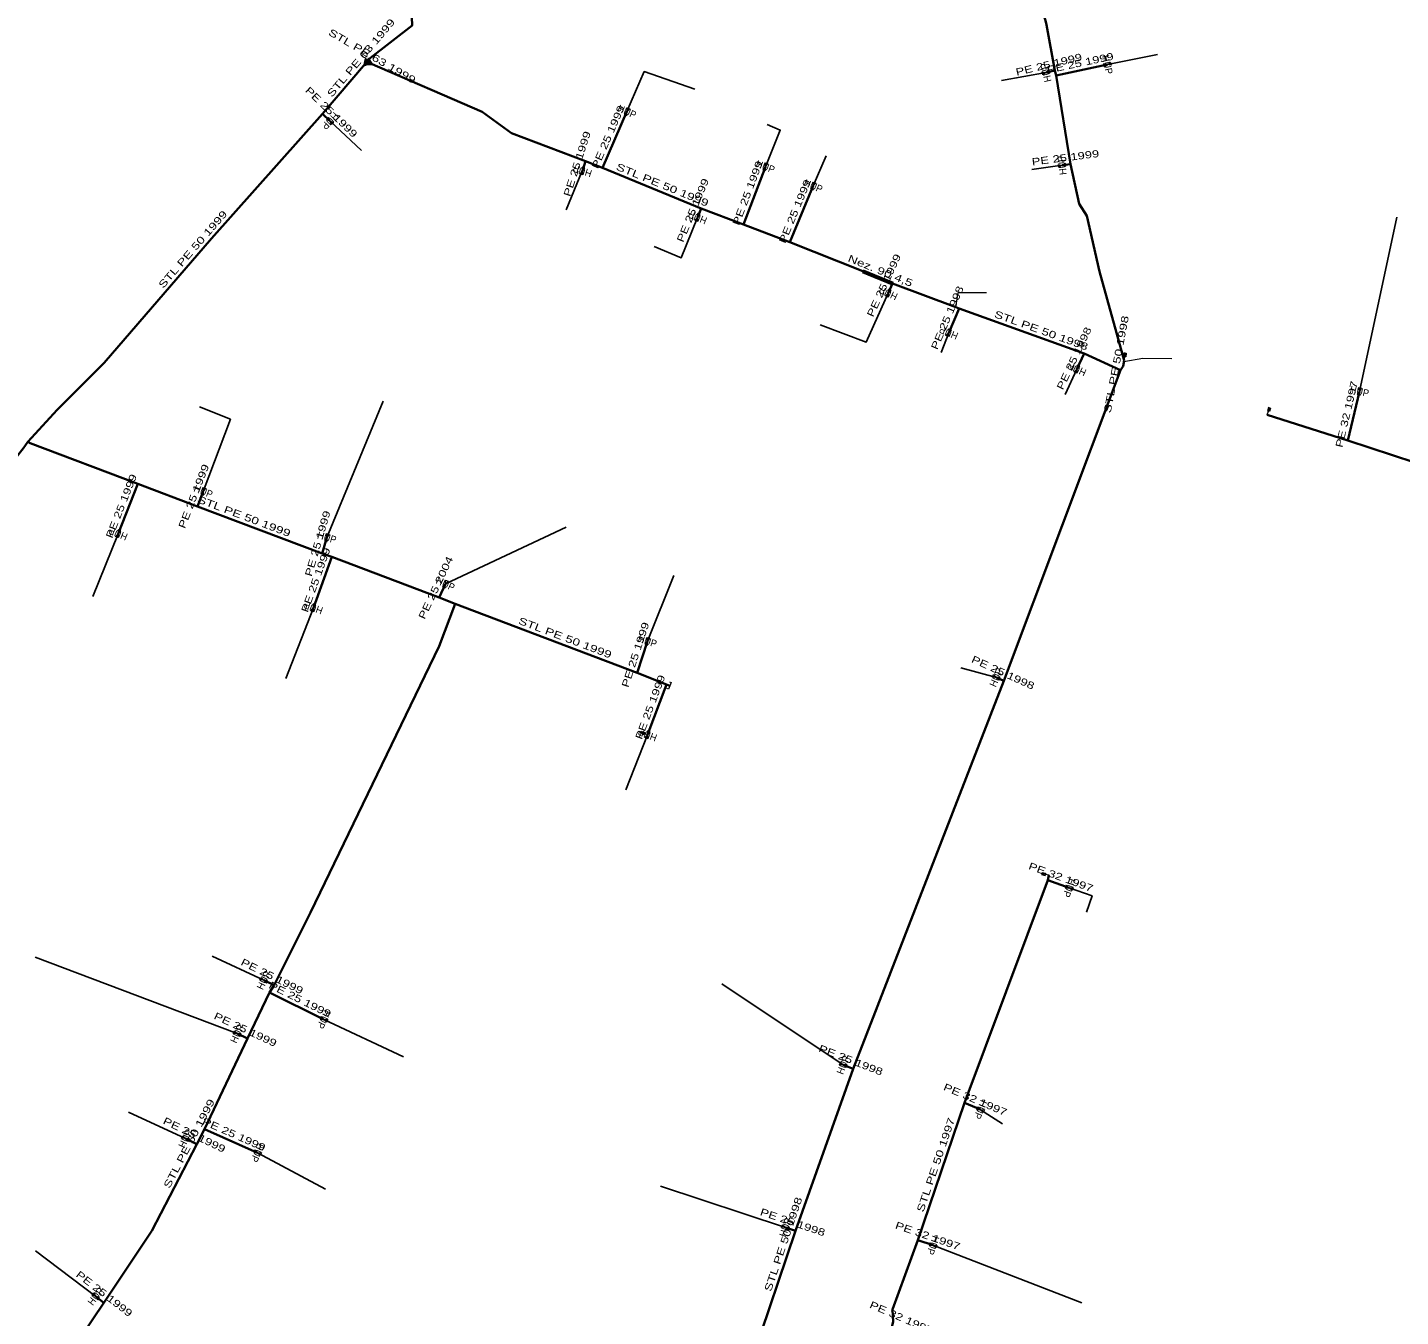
# Model space of a CAD drawing. Extents: x -737484 to -734496, y -1033882 to -1030666.
# Drawn here: x -736256.4 to -736065.4, y -1032475.7 to -1032296.4 of the extents above; entities that cross this region are included whole.
import ezdxf
from ezdxf.enums import TextEntityAlignment as Align

# ---------------------------------------------------------------- set-up
doc = ezdxf.new("R2010")
doc.units = 0
doc.header["$LTSCALE"] = 0.4
for name, color, linetype, lineweight in [('1', 7, 'Continuous', 13), ('18', 7, 'Continuous', 60), ('22', 7, 'Continuous', 25), ('5', 7, 'Continuous', 35), ('7', 7, 'Continuous', 35)]:
    doc.layers.add(name, color=color, linetype=linetype, lineweight=lineweight)
doc.layers.add('2', color=7, linetype='Continuous')

msp = doc.modelspace()

# ---------------------------------------------------------------- linework, layer by layer
at = {"layer": '1'}
for p, q in [((-736103.838, -1032342.709), (-736103.785, -1032342.211)), ((-736103.703, -1032342.144), (-736103.666, -1032341.796)), ((-736083.95, -1032350.269), (-736083.795, -1032349.793)), ((-736083.7, -1032349.745), (-736083.592, -1032349.412)), ((-736170.669, -1032394.513), (-736170.996, -1032394.388)), ((-736170.16, -1032394.79), (-736170.626, -1032394.61)), ((-736114.868, -1032414.107), (-736115.208, -1032414.022)), ((-736114.329, -1032414.319), (-736114.814, -1032414.198))]:
    msp.add_line(p, q, dxfattribs=at)
for points in [[(-736208.663, -1032301.356), (-736209.429, -1032300.713), (-736209.689, -1032301.801)], [(-736209.369, -1032300.894), (-736209.545, -1032301.629), (-736208.851, -1032301.328)], [(-736208.953, -1032300.696), (-736209.453, -1032301.563), (-736208.336, -1032301.63)], [(-736209.402, -1032301.458), (-736209.04, -1032301.301), (-736209.31, -1032301.074)], [(-736209.285, -1032301.472), (-736208.53, -1032301.518), (-736208.947, -1032300.887)], [(-736208.724, -1032301.406), (-736208.941, -1032301.077), (-736209.118, -1032301.383)], [(-736115.17, -1032302.994), (-736115.26, -1032302.604), (-736114.195, -1032302.769), (-736114.285, -1032302.379)], [(-736105.741, -1032301.288), (-736105.658, -1032301.679), (-736106.719, -1032301.496), (-736106.636, -1032301.887)], [(-736172.998, -1032307.58), (-736172.632, -1032307.743), (-736173.405, -1032308.494), (-736173.039, -1032308.657)], [(-736213.829, -1032309.612), (-736214.107, -1032309.9), (-736214.548, -1032308.917), (-736214.826, -1032309.205)], [(-736179.191, -1032316.915), (-736179.571, -1032316.791), (-736178.882, -1032315.964), (-736179.262, -1032315.84)], [(-736153.775, -1032315.24), (-736153.402, -1032315.383), (-736154.133, -1032316.174), (-736153.76, -1032316.317)], [(-736112.96, -1032315.849), (-736113.009, -1032315.452), (-736111.968, -1032315.727), (-736112.017, -1032315.33)], [(-736147.097, -1032317.921), (-736146.729, -1032318.077), (-736147.488, -1032318.842), (-736147.12, -1032318.998)], [(-736163.211, -1032323.387), (-736163.579, -1032323.231), (-736162.82, -1032322.466), (-736163.188, -1032322.31)], [(-736136.71, -1032333.915), (-736137.072, -1032333.746), (-736136.287, -1032333.009), (-736136.649, -1032332.84)], [(-736128.278, -1032339.416), (-736128.646, -1032339.26), (-736127.887, -1032338.495), (-736128.255, -1032338.339)], [(-736103.733, -1032341.714), (-736103.882, -1032341.698), (-736103.934, -1032342.196), (-736103.785, -1032342.211)], [(-736103.733, -1032341.714), (-736103.584, -1032341.73), (-736103.636, -1032342.227), (-736103.785, -1032342.211)], [(-736103.7, -1032341.756), (-736103.626, -1032341.763), (-736103.67, -1032342.186), (-736103.745, -1032342.178)], [(-736110.459, -1032344.474), (-736110.821, -1032344.305), (-736110.036, -1032343.568), (-736110.398, -1032343.399)], [(-736071.211, -1032346.496), (-736070.821, -1032346.586), (-736071.436, -1032347.471), (-736071.046, -1032347.561)], [(-736083.64, -1032349.317), (-736083.783, -1032349.271), (-736083.938, -1032349.747), (-736083.795, -1032349.793)], [(-736083.64, -1032349.317), (-736083.498, -1032349.364), (-736083.652, -1032349.839), (-736083.795, -1032349.793)], [(-736083.617, -1032349.365), (-736083.546, -1032349.388), (-736083.677, -1032349.792), (-736083.748, -1032349.769)], [(-736231.955, -1032360.389), (-736231.582, -1032360.532), (-736232.313, -1032361.323), (-736231.94, -1032361.466)], [(-736243.798, -1032367.366), (-736244.169, -1032367.216), (-736243.424, -1032366.439), (-736243.795, -1032366.289)], [(-736214.812, -1032366.812), (-736214.427, -1032366.922), (-736215.088, -1032367.773), (-736214.703, -1032367.883)], [(-736198.239, -1032373.272), (-736197.877, -1032373.441), (-736198.662, -1032374.178), (-736198.3, -1032374.347)], [(-736216.62, -1032377.667), (-736216.995, -1032377.53), (-736216.278, -1032376.727), (-736216.653, -1032376.59)], [(-736170.212, -1032381.239), (-736169.832, -1032381.363), (-736170.521, -1032382.19), (-736170.141, -1032382.314)], [(-736122.176, -1032386.788), (-736122.013, -1032386.422), (-736121.262, -1032387.195), (-736121.099, -1032386.829)], [(-736170.149, -1032395.328), (-736170.522, -1032395.185), (-736169.791, -1032394.394), (-736170.164, -1032394.251)], [(-736171.093, -1032394.431), (-736171.147, -1032394.571), (-736170.68, -1032394.75), (-736170.626, -1032394.61)], [(-736171.093, -1032394.431), (-736171.039, -1032394.291), (-736170.573, -1032394.47), (-736170.626, -1032394.61)], [(-736171.044, -1032394.41), (-736171.017, -1032394.34), (-736170.621, -1032394.492), (-736170.648, -1032394.563)], [(-736115.299, -1032414.077), (-736115.335, -1032414.222), (-736114.85, -1032414.343), (-736114.814, -1032414.198)], [(-736115.299, -1032414.077), (-736115.263, -1032413.931), (-736114.777, -1032414.052), (-736114.814, -1032414.198)], [(-736115.253, -1032414.05), (-736115.235, -1032413.977), (-736114.822, -1032414.08), (-736114.841, -1032414.153)], [(-736110.971, -1032416.053), (-736111.108, -1032416.428), (-736111.911, -1032415.711), (-736112.048, -1032416.086)], [(-736224.074, -1032428.878), (-736223.898, -1032428.519), (-736223.175, -1032429.316), (-736222.999, -1032428.957)], [(-736214.639, -1032434.397), (-736214.815, -1032434.756), (-736215.538, -1032433.959), (-736215.714, -1032434.318)], [(-736227.775, -1032436.317), (-736227.606, -1032435.955), (-736226.869, -1032436.74), (-736226.7, -1032436.378)], [(-736143.476, -1032440.695), (-736143.333, -1032440.322), (-736142.542, -1032441.053), (-736142.399, -1032440.68)], [(-736123.308, -1032446.925), (-736123.464, -1032447.293), (-736124.229, -1032446.534), (-736124.385, -1032446.902)], [(-736234.966, -1032450.898), (-736234.79, -1032450.539), (-736234.067, -1032451.336), (-736233.891, -1032450.977)], [(-736223.861, -1032452.928), (-736224.024, -1032453.294), (-736224.775, -1032452.521), (-736224.938, -1032452.887)], [(-736151.505, -1032463.313), (-736151.375, -1032462.935), (-736150.56, -1032463.638), (-736150.43, -1032463.26)], [(-736129.908, -1032465.753), (-736130.038, -1032466.131), (-736130.853, -1032465.428), (-736130.983, -1032465.806)], [(-736247.427, -1032472.728), (-736247.18, -1032472.413), (-736246.639, -1032473.344), (-736246.392, -1032473.029)]]:
    msp.add_lwpolyline(points, close=True, dxfattribs=at)
for points in [[(-736127.28, -1032335.31), (-736126.963, -1032333.293), (-736123.025, -1032333.293)], [(-736103.89, -1032342.85), (-736101.27, -1032342.406), (-736097.224, -1032342.432)], [(-736167.114, -1032387.412), (-736166.882, -1032387.506), (-736167.257, -1032388.433), (-736167.489, -1032388.339)]]:
    msp.add_lwpolyline(points, dxfattribs=at)
at = {"layer": '18'}
msp.add_line((-736140.229, -1032330.329), (-736136.058, -1032332.019), dxfattribs=at)
at = {"layer": '22'}
for p, q in [((-736106.19, -1032301.588), (-736099.223, -1032300.165)), ((-736114.728, -1032302.688), (-736120.899, -1032303.788)), ((-736214.329, -1032309.41), (-736209.967, -1032313.515)), ((-736147.11, -1032318.46), (-736145.317, -1032314.288)), ((-736112.489, -1032315.59), (-736116.692, -1032316.165)), ((-736179.228, -1032316.379), (-736181.489, -1032321.793)), ((-736071.129, -1032347.029), (-736065.919, -1032322.801)), ((-736128.268, -1032338.878), (-736129.325, -1032341.6)), ((-736110.429, -1032343.938), (-736112.085, -1032347.458)), ((-736214.76, -1032367.35), (-736206.954, -1032348.379)), ((-736243.798, -1032366.829), (-736247.309, -1032375.565)), ((-736198.27, -1032373.81), (-736181.477, -1032365.891)), ((-736170.179, -1032381.779), (-736166.519, -1032372.635)), ((-736216.638, -1032377.129), (-736220.46, -1032386.96)), ((-736121.638, -1032386.809), (-736126.561, -1032385.46)), ((-736170.158, -1032394.79), (-736173.19, -1032402.425)), ((-736227.238, -1032436.348), (-736255.33, -1032425.696)), ((-736223.538, -1032428.919), (-736230.736, -1032425.57)), ((-736142.938, -1032440.688), (-736159.802, -1032429.404)), ((-736215.178, -1032434.359), (-736204.081, -1032439.574)), ((-736234.429, -1032450.938), (-736242.334, -1032447.268)), ((-736123.85, -1032446.92), (-736120.79, -1032448.895)), ((-736224.4, -1032452.909), (-736214.946, -1032457.976)), ((-736150.969, -1032463.288), (-736168.337, -1032457.538)), ((-736246.91, -1032472.879), (-736255.316, -1032466.566)), ((-736130.45, -1032465.78), (-736109.749, -1032473.763))]:
    msp.add_line(p, q, dxfattribs=at)
for points in [[(-736173.019, -1032308.119), (-736170.61, -1032302.547), (-736163.59, -1032305.013)], [(-736153.769, -1032315.779), (-736151.694, -1032310.696), (-736153.516, -1032309.892)], [(-736163.2, -1032322.85), (-736165.466, -1032328.441), (-736169.217, -1032326.886)], [(-736136.68, -1032333.379), (-736139.744, -1032340.181), (-736146.121, -1032337.769)], [(-736231.949, -1032360.929), (-736228.189, -1032350.902), (-736232.501, -1032349.193)], [(-736111.51, -1032416.07), (-736108.315, -1032417.201), (-736109.112, -1032419.45)]]:
    msp.add_lwpolyline(points, dxfattribs=at)
at = {"layer": '5'}
for q in [(-736209.368, -1032301.418), (-736208.77, -1032301.38)]:
    msp.add_line((-736209.15, -1032301.16), q, dxfattribs=at)
for points in [[(-736103.84, -1032342.71), (-736107.29, -1032330.35), (-736109.04, -1032322.62), (-736110.11, -1032320.93), (-736111.31, -1032315.44), (-736113.32, -1032303.09), (-736113.48, -1032302.39), (-736114.65, -1032296.04), (-736114.78, -1032295.45), (-736116.57, -1032290.32), (-736122.27, -1032261.46), (-736124.19, -1032252.73), (-736126.74, -1032240.47), (-736127, -1032239.79), (-736129.39, -1032232.99), (-736131.29, -1032233.54)], [(-736184.22, -1032269.16), (-736188.09, -1032273.85), (-736203.08, -1032291.43), (-736202.89, -1032296.13), (-736208.68, -1032300.64), (-736209.15, -1032301.16)], [(-736209.368, -1032301.418), (-736215.35, -1032308.42), (-736230.8, -1032325.78), (-736245.75, -1032343.05), (-736252.28, -1032349.58), (-736256.34, -1032354.06)], [(-736208.77, -1032301.38), (-736193.14, -1032308.16), (-736189.09, -1032311.12), (-736178.78, -1032314.99), (-736176.44, -1032315.96), (-736162.68, -1032321.6), (-736156.82, -1032323.82), (-736150.37, -1032326.29), (-736140.23, -1032330.33), (-736136.06, -1032332.02), (-736127.28, -1032335.31)], [(-736104.36, -1032344.1), (-736109.41, -1032341.78), (-736126.82, -1032335.48), (-736127.28, -1032335.31)], [(-736103.84, -1032342.71), (-736103.99, -1032343.51), (-736104.36, -1032344.1)], [(-736104.36, -1032344.1), (-736120.6, -1032387.28), (-736141.54, -1032441.23), (-736149.59, -1032463.75), (-736161.52, -1032499.18), (-736165.67, -1032508.99), (-736179.12, -1032543.22), (-736187.51, -1032561.02), (-736199.17, -1032586.55)], [(-735976.37, -1032383.6), (-735978.61, -1032382.76), (-735988.28, -1032380.4), (-736008.36, -1032374.75), (-736015.25, -1032372.36), (-736036.94, -1032365.45), (-736039.11, -1032364.77), (-736054.11, -1032359.99), (-736072.75, -1032353.85), (-736083.95, -1032350.27)], [(-736256.34, -1032354.06), (-736257.03, -1032354.95), (-736260.59, -1032359.44), (-736272.46, -1032371.63), (-736285.72, -1032384.95), (-736298.08, -1032397.54), (-736305.52, -1032405.1), (-736312.78, -1032412.28), (-736323.22, -1032423.701), (-736333.96, -1032435.45), (-736335.03, -1032436.63), (-736344.49, -1032446.8), (-736353.42, -1032456.59), (-736361.22, -1032465.02), (-736362.27, -1032466.2)], [(-736256.34, -1032354.06), (-736256.04, -1032354.24), (-736241.05, -1032359.87), (-736232.76, -1032363.02), (-736215.41, -1032369.58), (-736214.09, -1032370.041), (-736199.161, -1032375.709), (-736196.92, -1032376.56)], [(-736196.92, -1032376.56), (-736199.16, -1032382.48), (-736217.04, -1032419.51), (-736222.11, -1032429.62), (-736222.72, -1032430.62), (-736225.79, -1032437.02), (-736231.78, -1032449.63), (-736232.84, -1032451.71), (-736239.11, -1032463.78), (-736245.77, -1032473.76), (-736254.77, -1032487.12), (-736256.92, -1032490.44), (-736274.19, -1032514.26), (-736279.5, -1032521.66)], [(-736196.92, -1032376.56), (-736171.61, -1032386.15), (-736167.53, -1032387.78), (-736167.07, -1032387.97)], [(-736141.03, -1032495.44), (-736140.64, -1032494.62), (-736141.54, -1032494.2), (-736137.92, -1032483.69), (-736136, -1032476.43), (-736136.06, -1032474.71), (-736132.56, -1032465.05), (-736126.07, -1032445.97), (-736114.49, -1032414.98), (-736114.33, -1032414.32)]]:
    msp.add_lwpolyline(points, dxfattribs=at)
at = {"layer": '7'}
for p, q in [((-736113.48, -1032302.39), (-736114.728, -1032302.687)), ((-736113.32, -1032303.09), (-736106.189, -1032301.588)), ((-736176.44, -1032315.96), (-736173.019, -1032308.119)), ((-736215.35, -1032308.42), (-736214.328, -1032309.409)), ((-736178.78, -1032314.99), (-736179.227, -1032316.378)), ((-736156.82, -1032323.82), (-736153.768, -1032315.779)), ((-736111.31, -1032315.44), (-736112.489, -1032315.59)), ((-736150.37, -1032326.29), (-736147.109, -1032318.46)), ((-736162.68, -1032321.6), (-736163.2, -1032322.849)), ((-736136.06, -1032332.02), (-736136.68, -1032333.378)), ((-736126.82, -1032335.48), (-736128.267, -1032338.878)), ((-736109.41, -1032341.78), (-736110.429, -1032343.937)), ((-736072.75, -1032353.85), (-736071.129, -1032347.029)), ((-736241.05, -1032359.87), (-736243.797, -1032366.828)), ((-736232.76, -1032363.02), (-736231.948, -1032360.928)), ((-736215.41, -1032369.58), (-736214.758, -1032367.348)), ((-736214.09, -1032370.041), (-736216.637, -1032377.129)), ((-736199.161, -1032375.709), (-736198.27, -1032373.81)), ((-736171.61, -1032386.15), (-736170.177, -1032381.777)), ((-736167.53, -1032387.78), (-736170.157, -1032394.79)), ((-736120.6, -1032387.28), (-736121.638, -1032386.809)), ((-736114.49, -1032414.98), (-736111.51, -1032416.07)), ((-736222.11, -1032429.62), (-736223.537, -1032428.918)), ((-736222.72, -1032430.62), (-736215.177, -1032434.358)), ((-736225.79, -1032437.02), (-736227.238, -1032436.348)), ((-736141.54, -1032441.23), (-736142.938, -1032440.688)), ((-736126.07, -1032445.97), (-736123.847, -1032446.914)), ((-736231.78, -1032449.63), (-736224.4, -1032452.908)), ((-736232.84, -1032451.71), (-736234.429, -1032450.938)), ((-736149.59, -1032463.75), (-736150.968, -1032463.287)), ((-736132.56, -1032465.05), (-736130.446, -1032465.78)), ((-736245.77, -1032473.76), (-736246.91, -1032472.879))]:
    msp.add_line(p, q, dxfattribs=at)

# ---------------------------------------------------------------- texts
at = {"layer": '18', "width": 1.4}
msp.add_text('Nez. 90 4,5', height=1, rotation=337.943, dxfattribs=at).set_placement((-736137.9553, -1032330.7105), align=Align.CENTER)
at = {"layer": '2', "width": 0.95}
for rotation, p in [(282, (-736106.6772, -1032301.6915)), (103, (-736114.2405, -1032302.574)), (226, (-736214.6874, -1032309.0612)), (336, (-736173.2219, -1032308.5757)), (162, (-736179.072, -1032315.902)), (339, (-736153.9467, -1032316.2453)), (97, (-736111.9927, -1032315.5284)), (337, (-736147.3039, -1032318.9193)), (157, (-736163.0041, -1032322.3887)), (155, (-736136.4682, -1032332.9244)), (157, (-736128.0711, -1032338.4177)), (155, (-736110.2172, -1032343.4834)), (347, (-736071.241, -1032347.5155)), (339, (-736232.1267, -1032361.3943)), (158, (-736243.6092, -1032366.364)), (344, (-736214.8953, -1032367.8278)), (335, (-736198.4808, -1032374.2626)), (160, (-736216.4655, -1032376.6583)), (342, (-736170.331, -1032382.252)), (66, (-736121.1803, -1032387.0119)), (159, (-736169.9773, -1032394.3227)), (250, (-736111.9797, -1032415.8985)), (64, (-736223.0875, -1032429.1367)), (244, (-736215.6255, -1032434.1383)), (65, (-736226.7844, -1032436.5588)), (69, (-736142.4707, -1032440.8667)), (247, (-736124.3063, -1032446.7181)), (64, (-736233.9795, -1032451.1567)), (246, (-736224.8567, -1032452.7041)), (71, (-736150.495, -1032463.4493)), (251, (-736130.918, -1032465.6167)), (52, (-736246.515, -1032473.1863))]:
    msp.add_text('HUP', height=1, rotation=rotation, dxfattribs=at).set_placement(p, align=Align.CENTER)
at = {"layer": '5', "width": 1.4}
for s, rotation, p in [('STL PE 63 1999', 49.803, (-736209.64, -1032300.9657)), ('STL PE 63 1999', 329.931, (-736208.709, -1032300.8364)), ('STL PE 50 1999', 337.712, (-736168.2756, -1032318.7656)), ('STL PE 50 1999', 49.118, (-736233.0342, -1032327.5972)), ('STL PE 50 1998', 340.107, (-736115.5616, -1032339.0211)), ('STL PE 50 1998', 79.38, (-736104.4699, -1032343.3596)), ('STL PE 50 1999', 339.288, (-736226.4643, -1032364.8649)), ('STL PE 50 1999', 339.248, (-736181.8002, -1032381.7533)), ('STL PE 50 1999', 62.549, (-736233.483, -1032451.8645)), ('STL PE 50 1997', 71.214, (-736129.5888, -1032454.7615)), ('STL PE 50 1998', 71.391, (-736150.8034, -1032465.7886))]:
    msp.add_text(s, height=1, rotation=rotation, dxfattribs=at).set_placement(p, align=Align.CENTER)
at = {"layer": '7', "width": 1.35}
for s, rotation, p in [('PE 25 1999', 13.386, (-736114.2198, -1032302.052)), ('PE 25 1999', 11.894, (-736109.8571, -1032301.8489)), ('PE 25 1999', 315.94, (-736214.4907, -1032308.554)), ('PE 25 1999', 66.429, (-736175.1869, -1032311.8394)), ('PE 25 1999', 72.149, (-736179.479, -1032315.5303)), ('PE 25 1999', 7.251, (-736111.9626, -1032315.0184)), ('PE 25 1999', 69.216, (-736155.7611, -1032319.6214)), ('PE 25 1999', 67.396, (-736163.4015, -1032322.0317)), ('PE 25 1999', 67.389, (-736149.2011, -1032322.1822)), ('PE 25 1999', 65.461, (-736136.824, -1032332.4907)), ('PE 25 1998', 66.934, (-736128.0029, -1032336.9829)), ('PE 25 1998', 64.713, (-736110.371, -1032342.6446)), ('PE 32 1997', 76.632, (-736072.4254, -1032350.3231)), ('PE 25 1999', 68.787, (-736232.8196, -1032361.7924)), ('PE 25 1999', 68.456, (-736242.8877, -1032363.1651)), ('PE 25 1999', 73.716, (-736215.5633, -1032368.3232)), ('PE 25 1999', 70.235, (-736215.8331, -1032373.4156)), ('PE 25 2004', 64.864, (-736199.1675, -1032374.5464)), ('PE 25 1999', 71.856, (-736171.3686, -1032383.8077)), ('PE 25 1998', 335.593, (-736120.9121, -1032386.5889)), ('PE 25 1999', 69.456, (-736169.3109, -1032391.109)), ('PE 32 1997', 339.909, (-736112.8278, -1032415.0546)), ('PE 25 1999', 333.806, (-736222.6022, -1032428.8202)), ('PE 25 1999', 333.639, (-736218.726, -1032432.0409)), ('PE 25 1999', 335.105, (-736226.303, -1032436.2302)), ('PE 25 1998', 338.809, (-736142.0577, -1032440.4927)), ('PE 32 1997', 336.991, (-736124.7629, -1032445.9817)), ('PE 25 1999', 334.088, (-736233.4155, -1032450.8741)), ('PE 25 1999', 336.05, (-736227.8865, -1032450.8119)), ('PE 25 1998', 341.428, (-736150.1192, -1032463.0444)), ('PE 32 1997', 340.949, (-736131.3392, -1032464.9413)), ('PE 25 1999', 322.303, (-736246.0337, -1032472.9235)), ('PE 32 1997', 336.518, (-736135.0452, -1032476.2993))]:
    msp.add_text(s, height=1, rotation=rotation, dxfattribs=at).set_placement(p, align=Align.CENTER)

doc.saveas('drawing.dxf')
